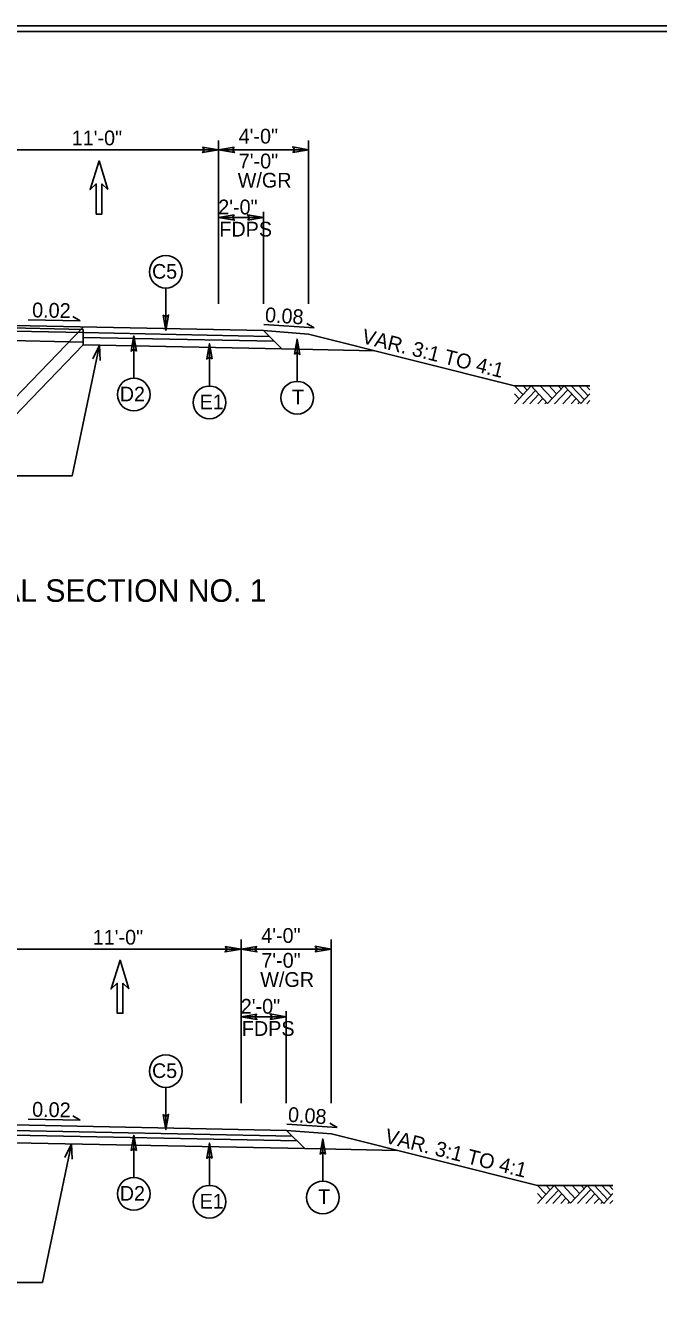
# Model space of a CAD drawing. Extents: x 1901718 to 1902220, y 193828 to 194187.
# Drawn here: x 1902059.1 to 1902087.2, y 193988.8 to 194045.8 of the extents above; entities that cross this region are included whole.
import ezdxf

# ---------------------------------------------------------------- set-up
doc = ezdxf.new("R2010")
doc.units = 0
for name, color, linetype in [('Old_Level_1', 7, 'Continuous'), ('Old_Level_11', 7, 'Continuous'), ('Old_Level_2', 7, 'Continuous'), ('Old_Level_20', 7, 'Continuous'), ('Prop Dimension', 7, 'Continuous'), ('Prop Dimension Text', 7, 'Continuous'), ('Sheet Border Standard 30in CELL', 7, 'Continuous'), ('Sheet Plot Border Inside CELL', 7, 'Continuous'), ('Typical Terminator CELL', 7, 'Continuous')]:
    doc.layers.add(name, color=color, linetype=linetype)

# ---------------------------------------------------------------- blocks, each defined once
blk = doc.blocks.new('TERMINATOR')
at = {"layer": 'Typical Terminator CELL'}
blk.add_lwpolyline([(-0.469, 0.081), (0, 0), (-0.471, -0.083), (-0.411, 0)], close=True, dxfattribs=at)

msp = doc.modelspace()

# ---------------------------------------------------------------- linework, layer by layer
at = {"layer": 'Old_Level_1'}
for p, q in [((1902050.692, 194032.619), (1902069.692, 194032.239)), ((1902059.255, 194032.722), (1902061.559, 194032.674)), ((1902061.559, 194032.674), (1902061.237, 194032.86)), ((1902050.692, 194032.515), (1902061.692, 194032.295)), ((1902050.692, 194032.369), (1902061.692, 194032.149)), ((1902061.692, 194032.399), (1902057.216, 194027.774)), ((1902061.692, 194032.295), (1902061.692, 194031.607)), ((1902061.692, 194032.149), (1902069.948, 194031.984)), ((1902069.692, 194032.239), (1902071.692, 194032.079)), ((1902069.692, 194032.239), (1902070.5, 194031.431)), ((1902069.705, 194032.515), (1902071.94, 194032.369)), ((1902071.94, 194032.369), (1902071.618, 194032.555)), ((1902071.692, 194032.079), (1902080.827, 194029.795)), ((1902050.692, 194031.953), (1902061.692, 194031.733)), ((1902061.692, 194031.607), (1902057.216, 194026.982)), ((1902061.692, 194031.94), (1902070.16, 194031.771)), ((1902061.692, 194031.607), (1902070.5, 194031.431)), ((1902070.5, 194031.431), (1902074.613, 194031.348)), ((1902080.827, 194029.795), (1902081.202, 194029.392)), ((1902080.827, 194028.99), (1902081.569, 194029.787)), ((1902081.202, 194029.795), (1902081.389, 194029.594)), ((1902081.569, 194029.787), (1902082.293, 194029.008)), ((1902081.96, 194029.795), (1902082.493, 194029.222)), ((1902082.293, 194029.008), (1902083.024, 194029.794)), ((1902082.358, 194029.795), (1902082.691, 194029.436)), ((1902082.76, 194029.795), (1902082.893, 194029.652)), ((1902083.024, 194029.794), (1902083.765, 194028.998)), ((1902083.346, 194029.795), (1902083.926, 194029.172)), ((1902083.679, 194029.795), (1902084.093, 194029.351)), ((1902083.999, 194029.795), (1902084.169, 194029.612)), ((1902080.827, 194029.433), (1902081.033, 194029.211)), ((1902081.201, 194028.99), (1902081.755, 194029.586)), ((1902081.51, 194028.99), (1902081.911, 194029.419)), ((1902081.857, 194028.99), (1902082.084, 194029.233)), ((1902082.603, 194028.99), (1902083.189, 194029.618)), ((1902082.973, 194028.99), (1902083.373, 194029.419)), ((1902083.339, 194028.99), (1902083.556, 194029.223)), ((1902083.765, 194028.998), (1902084.169, 194029.433)), ((1902082.168, 194028.99), (1902082.239, 194029.066)), ((1902083.634, 194028.99), (1902083.703, 194029.064)), ((1902084.035, 194028.99), (1902084.169, 194029.133)), ((1902059.255, 193997.254), (1902061.559, 193997.206)), ((1902061.559, 193997.206), (1902061.237, 193997.392)), ((1902050.692, 193997.151), (1902070.713, 193996.75)), ((1902050.692, 193996.901), (1902070.968, 193996.495)), ((1902050.692, 193996.692), (1902071.181, 193996.282)), ((1902070.713, 193996.75), (1902072.713, 193996.59)), ((1902070.713, 193996.75), (1902071.521, 193995.942)), ((1902070.725, 193997.026), (1902072.96, 193996.881)), ((1902072.96, 193996.881), (1902072.638, 193997.067)), ((1902050.692, 193996.359), (1902071.521, 193995.942)), ((1902072.713, 193996.59), (1902081.848, 193994.307)), ((1902071.521, 193995.942), (1902075.634, 193995.86)), ((1902081.848, 193994.307), (1902082.223, 193993.904)), ((1902081.848, 193993.502), (1902082.59, 193994.299)), ((1902081.848, 193993.945), (1902082.054, 193993.723)), ((1902082.222, 193993.502), (1902082.776, 193994.098)), ((1902082.223, 193994.307), (1902082.41, 193994.106)), ((1902082.531, 193993.502), (1902082.932, 193993.931)), ((1902082.59, 193994.299), (1902083.314, 193993.52)), ((1902082.981, 193994.307), (1902083.514, 193993.734)), ((1902083.314, 193993.52), (1902084.045, 193994.306)), ((1902083.379, 193994.307), (1902083.712, 193993.948)), ((1902083.624, 193993.502), (1902084.21, 193994.13)), ((1902083.781, 193994.307), (1902083.914, 193994.164)), ((1902083.994, 193993.502), (1902084.394, 193993.931)), ((1902084.045, 193994.306), (1902084.786, 193993.51)), ((1902084.367, 193994.307), (1902084.947, 193993.684)), ((1902084.7, 193994.307), (1902085.114, 193993.863)), ((1902084.786, 193993.51), (1902085.19, 193993.945)), ((1902085.02, 193994.307), (1902085.19, 193994.124)), ((1902082.878, 193993.502), (1902083.105, 193993.745)), ((1902083.189, 193993.502), (1902083.26, 193993.578)), ((1902084.36, 193993.502), (1902084.577, 193993.735)), ((1902084.655, 193993.502), (1902084.724, 193993.576)), ((1902085.056, 193993.502), (1902085.19, 193993.645))]:
    msp.add_line(p, q, dxfattribs=at)
for points in [[(1902062.414, 194031.592), (1902061.2, 194025.788), (1902055.809, 194025.788)], [(1902062.121, 194030.983), (1902062.414, 194031.592), (1902062.442, 194030.917)], [(1902080.827, 194029.795), (1902084.169, 194029.795)], [(1902061.17, 193996.149), (1902059.885, 193990.006), (1902054.494, 193990.006)], [(1902060.877, 193995.54), (1902061.17, 193996.149), (1902061.198, 193995.474)], [(1902081.848, 193994.307), (1902085.19, 193994.307)]]:
    msp.add_lwpolyline(points, dxfattribs=at)
at = {"layer": 'Old_Level_11'}
for p, q in [((1902065.358, 194034.125), (1902065.358, 194032.251)), ((1902063.933, 194030.129), (1902063.933, 194032.003)), ((1902067.292, 194029.781), (1902067.292, 194031.655)), ((1902071.182, 194029.987), (1902071.182, 194031.862)), ((1902071.182, 194029.987), (1902071.182, 194031.862)), ((1902065.358, 193998.657), (1902065.358, 193996.783)), ((1902063.933, 193994.661), (1902063.933, 193996.535)), ((1902067.292, 193994.312), (1902067.292, 193996.187)), ((1902072.322, 193994.499), (1902072.322, 193996.373))]:
    msp.add_line(p, q, dxfattribs=at)
for points in [[(1902065.242, 194032.922), (1902065.358, 194032.251), (1902065.477, 194032.926), (1902065.358, 194032.84)], [(1902064.049, 194031.332), (1902063.933, 194032.003), (1902063.814, 194031.328), (1902063.933, 194031.414)], [(1902067.408, 194030.983), (1902067.292, 194031.655), (1902067.173, 194030.98), (1902067.292, 194031.065)], [(1902071.067, 194031.19), (1902071.182, 194031.862), (1902071.302, 194031.186), (1902071.182, 194031.272)], [(1902071.067, 194031.19), (1902071.182, 194031.862), (1902071.302, 194031.186), (1902071.182, 194031.272)], [(1902065.242, 193997.454), (1902065.358, 193996.783), (1902065.477, 193997.458), (1902065.358, 193997.372)], [(1902064.049, 193995.864), (1902063.933, 193996.535), (1902063.814, 193995.86), (1902063.933, 193995.946)], [(1902067.408, 193995.515), (1902067.292, 193996.187), (1902067.173, 193995.511), (1902067.292, 193995.597)], [(1902072.437, 193995.702), (1902072.322, 193996.373), (1902072.202, 193995.698), (1902072.322, 193995.784)]]:
    msp.add_lwpolyline(points, close=True, dxfattribs=at)
for centre in [(1902065.358, 194034.85), (1902063.933, 194029.404), (1902067.292, 194029.055), (1902071.183, 194029.262), (1902071.183, 194029.262), (1902065.358, 193999.382), (1902063.933, 193993.936), (1902072.322, 193993.774), (1902067.292, 193993.587)]:
    msp.add_circle(centre, 0.725, dxfattribs=at)
at = {"layer": 'Prop Dimension'}
for p, q in [((1902067.692, 194033.43), (1902067.692, 194040.682)), ((1902071.692, 194033.43), (1902071.692, 194040.682)), ((1902056.692, 194040.263), (1902067.692, 194040.263)), ((1902069.692, 194037.259), (1902067.692, 194037.259)), ((1902069.692, 194033.43), (1902069.692, 194037.509)), ((1902057.692, 194004.795), (1902068.692, 194004.795)), ((1902068.692, 193997.962), (1902068.692, 194005.214)), ((1902072.692, 193997.962), (1902072.692, 194005.214)), ((1902070.692, 193997.962), (1902070.692, 194002.041)), ((1902070.692, 194001.791), (1902068.692, 194001.791))]:
    msp.add_line(p, q, dxfattribs=at)
for points in [[(1902062.79, 194038.497), (1902062.519, 194038.747), (1902062.519, 194037.413), (1902062.269, 194037.413), (1902062.269, 194038.747), (1902061.998, 194038.497), (1902062.394, 194039.767)], [(1902062.79, 194038.497), (1902062.519, 194038.747), (1902062.519, 194037.413), (1902062.269, 194037.413), (1902062.269, 194038.747), (1902061.998, 194038.497), (1902062.394, 194039.767)], [(1902063.722, 194003.029), (1902063.451, 194003.279), (1902063.451, 194001.945), (1902063.201, 194001.945), (1902063.201, 194003.279), (1902062.931, 194003.029), (1902063.326, 194004.299)], [(1902063.722, 194003.029), (1902063.451, 194003.279), (1902063.451, 194001.945), (1902063.201, 194001.945), (1902063.201, 194003.279), (1902062.931, 194003.029), (1902063.326, 194004.299)]]:
    msp.add_lwpolyline(points, close=True, dxfattribs=at)
at = {"layer": 'Prop Dimension Text'}
for p, q in [((1902071.692, 194040.263), (1902067.692, 194040.263)), ((1902072.692, 194004.795), (1902068.692, 194004.795))]:
    msp.add_line(p, q, dxfattribs=at)
at = {"layer": 'Sheet Border Standard 30in CELL'}
msp.add_lwpolyline([(1902132.544, 194045.514), (1901982.544, 194045.514), (1901982.544, 193940.514), (1902132.544, 193940.514)], close=True, dxfattribs=at)
at = {"layer": 'Sheet Plot Border Inside CELL'}
msp.add_lwpolyline([(1902133.794, 194045.769), (1901967.144, 194045.769), (1901967.144, 193940.259), (1902133.794, 193940.259)], close=True, dxfattribs=at)

# ---------------------------------------------------------------- block references
at = {"layer": 'Prop Dimension', "xscale": 1.5}
for p, yscale in [((1902067.692, 194040.263), 1.5), ((1902071.692, 194040.263), -1.5), ((1902069.692, 194037.259), -1.5), ((1902068.692, 194004.795), 1.5), ((1902072.692, 194004.795), -1.5), ((1902070.692, 194001.791), -1.5)]:
    msp.add_blockref('TERMINATOR', p, dxfattribs=dict(at, yscale=yscale))
at = {"layer": 'Prop Dimension', "xscale": 1.5, "yscale": -1.5, "rotation": -180}
for p in [(1902067.692, 194040.263), (1902067.692, 194037.259), (1902068.692, 194004.795), (1902068.692, 194001.791)]:
    msp.add_blockref('TERMINATOR', p, dxfattribs=at)

# ---------------------------------------------------------------- texts
at = {"layer": 'Old_Level_1'}
for p in [(1902074.008, 194031.695), (1902075.029, 193996.206)]:
    msp.add_text('VAR. 3:1 TO 4:1', height=0.656, rotation=345.9638, dxfattribs=at).set_placement(p)
at = {"layer": 'Old_Level_11'}
msp.add_text('TRANSITION FROM EXISTING TO TYPICAL SECTION NO. 1', height=1, dxfattribs=at).set_placement((1902032.45, 194020.204))
at = {"layer": 'Old_Level_2'}
for s, rotation, p in [('0.02', 358.8084, (1902059.421, 194032.83)), ('0.08', 356.2834, (1902069.741, 194032.623)), ('0.02', 358.8084, (1902059.421, 193997.362)), ('0.08', 356.2834, (1902070.761, 193997.135))]:
    msp.add_text(s, height=0.656, rotation=rotation, dxfattribs=at).set_placement(p)
at = {"layer": 'Old_Level_20'}
for s, height, p in [('C5', 0.6491, (1902064.747, 194034.544)), ('D2', 0.6491, (1902063.319, 194029.1)), ('E1', 0.6491, (1902066.859, 194028.752)), ('T', 0.649, (1902070.955, 194028.969)), ('T', 0.649, (1902070.955, 194028.969)), ('C5', 0.6491, (1902064.747, 193999.076)), ('D2', 0.6491, (1902063.319, 193993.632)), ('E1', 0.6491, (1902066.859, 193993.284)), ('T', 0.649, (1902072.111, 193993.481))]:
    msp.add_text(s, height=height, dxfattribs=at).set_placement(p)
at = {"layer": 'Prop Dimension'}
for s, p in [('11\'-0" ', (1902061.182, 194040.461)), ('2\'-0"', (1902067.682, 194037.396)), ('FDPS', (1902067.729, 194036.412)), ('11\'-0" ', (1902062.115, 194004.993)), ('2\'-0"', (1902068.682, 194001.928)), ('FDPS', (1902068.729, 194000.944))]:
    msp.add_text(s, height=0.656, dxfattribs=at).set_placement(p)
at = {"layer": 'Prop Dimension Text'}
for s, p in [('4\'-0"', (1902068.589, 194040.538)), ('7\'-0"', (1902068.593, 194039.437)), ('W/GR', (1902068.546, 194038.584)), ('4\'-0"', (1902069.589, 194005.07)), ('7\'-0"', (1902069.593, 194003.969)), ('W/GR', (1902069.546, 194003.116))]:
    msp.add_text(s, height=0.656, dxfattribs=at).set_placement(p)

doc.saveas('drawing.dxf')
